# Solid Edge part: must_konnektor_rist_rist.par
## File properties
Author: Romil
Template: iso part.par
Last saved by: Romil
Revision: 24
Application: Solid Edge
Accuracy: 0.990
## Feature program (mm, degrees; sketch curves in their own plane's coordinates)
sketch for "unnamed Protrusion 1" plane through (0, 0, 0) normal (1, 0, 0) x-axis (0, 1, 0)
  circle centre (0, 0) radius 3.35
extrude "unnamed Protrusion 1" add finite 16 symmetric
sketch for "ExtrudedCutout_1" plane through (0, 0, 0) normal (1, 0, 0) x-axis (0, 1, 0)
  circle centre (0, 0) radius 2.55
extrude "ExtrudedCutout_1" cut finite 26.4602 symmetric
sketch for "ExtrudedProtrusion_2" plane through (0, 0, 0) normal (1, 0, 0) x-axis (0, 1, 0)
  circle centre (0, 0) radius 2.85
extrude "ExtrudedProtrusion_2" add finite 1.56 symmetric
sketch for "ExtrudedCutout_2" plane through (0, 0, 0) normal (1, 0, 0) x-axis (0, 1, 0)
  circle centre (0, 0) radius 1.5
extrude "ExtrudedCutout_2" cut finite 517.645 symmetric
sketch for "unnamed Protrusion 2" plane through (-8, 0, 0) normal (-1, 0, 0) x-axis (0, -1, 0)
  line (-1.1715, -2.55) -> (1.1715, -2.55)
  line (1.2205, -2.55) -> (1.1715, -2.55)
  line (1.2763, -2.55) -> (1.2205, -2.55)
  line (0.6382, -1.9118) -> (1.2763, -2.55)
  line (-0.6382, -1.9118) -> (-1.2763, -2.55)
  line (-1.2763, -2.55) -> (-1.2205, -2.55)
  line (-1.2205, -2.55) -> (-1.1715, -2.55)
extrude "unnamed Protrusion 2" add to key point along -normal
mirror "unnamed Mirror 1" of "unnamed Protrusion 2" about plane through (0, 0, 0) normal (0, 0, 1)
extrude "unnamed Protrusion 3" add finite 16
sketch for "unnamed Protrusion 4" plane through (-8, 0, 0) normal (-1, 0, 0) x-axis (0, -1, 0)
  arc centre (-1.65, 0) radius 0.15 from (-1.5, 0) to (-1.65, 0.15) ccw
  line (-1.65, 0.15) -> (-3.1, 0.15)
  line (-3.1, 0.15) -> (-3.1, -0.15)
  line (-3.1, -0.15) -> (-1.65, -0.15)
  arc centre (-1.65, 0) radius 0.15 from (-1.65, -0.15) to (-1.5, 0) ccw
extrude "unnamed Protrusion 4" add to key point along -normal
mirror "unnamed Mirror 2" of "unnamed Protrusion 4" about plane through (0, 0, 0) normal (0, -1, 0)
extrude "unnamed Protrusion 5" add finite 16
sketch for "ExtrudedCutout_3" plane through (-8, 0, 0) normal (-1, 0, 0) x-axis (0, -1, 0)
  circle centre (3.9391, 3.9391) radius 2.45
extrude "ExtrudedCutout_3" cut finite 274.7271 symmetric
mirror "unnamed Mirror 3" of "ExtrudedCutout_3" about plane through (0, 0, 0) normal (0, -1, 0)
extrude "unnamed Cutout 1" cut finite 274.7271 symmetric
mirror "unnamed Mirror 4" of "ExtrudedCutout_3", "unnamed Mirror 3" about plane through (0, 0, 0) normal (0, 0, 1)
extrude "unnamed Cutout 2" cut finite 274.7271 symmetric
extrude "unnamed Cutout 3" cut finite 274.7271 symmetric
sketch for "ExtrudedCutout_7" plane through (-8, 0, 0) normal (-1, 0, 0) x-axis (0, -1, 0)
  line (-3.15, -3.7941) -> (-3.15, 4.9513)
  line (-3.15, 4.9513) -> (-5.3224, 4.9513)
  line (-5.3224, 4.9513) -> (-5.3224, -3.7941)
  line (-5.3224, -3.7941) -> (-3.15, -3.7941)
extrude "ExtrudedCutout_7" cut finite 49.4886 symmetric
mirror "unnamed Mirror 5" of "ExtrudedCutout_7" about plane through (0, 0, 0) normal (0, -1, 0)
extrude "unnamed Cutout 4" cut finite 49.4886 symmetric
fillet "Round_2" radius 0.5
sketch for "unnamed RevolvedProtrusion 1" plane through (0, 0, 0) normal (0, -1, 0) x-axis (1, 0, 0)
  line (0.086, 3.4049) -> (0.4761, 2.7468)
  line (0.4761, 2.7468) -> (0, 2.7468)
  line (-0.4761, 2.7468) -> (0, 2.7468)
  line (-0.086, 3.4049) -> (-0.4761, 2.7468)
  arc centre (0, 3.3539) radius 0.1 from (-0.086, 3.4049) to (0.086, 3.4049) cw
revolve "unnamed RevolvedProtrusion 1" add finite 360 deg
pattern "unnamed Pattern 1" of "unnamed RevolvedProtrusion 1"
revolve "unnamed RevolvedProtrusion 2" add finite 360 deg
revolve "unnamed RevolvedProtrusion 3" add finite 360 deg
sketch for "ExtrudedCutout_16" plane through (8, 0, 0) normal (1, 0, 0) x-axis (0, 0, -1)
  line (-3.512, -1.8908) -> (-1.8908, -3.512)
  arc centre (-3.2512, -3.1128) radius 1.4178 from (-2.0078, -2.4316) to (-1.8908, -3.512) cw
  arc centre (-3.9391, -3.9391) radius 2.45 from (-2.4316, -2.0078) to (-2.0078, -2.4316) cw
  arc centre (-3.1128, -3.2512) radius 1.4178 from (-2.4316, -2.0078) to (-3.512, -1.8908) ccw
extrude "ExtrudedCutout_16" cut finite 89.8858 symmetric
mirror "unnamed Mirror 6" of "ExtrudedCutout_16" about plane through (0, 0, 0) normal (0, 0, 1)
extrude "unnamed Cutout 5" cut finite 89.8858 symmetric
mirror "unnamed Mirror 7" of "ExtrudedCutout_16", "unnamed Mirror 6" about plane through (0, 0, 0) normal (0, -1, 0)
extrude "unnamed Cutout 6" cut finite 89.8858 symmetric
extrude "unnamed Cutout 7" cut finite 89.8858 symmetric
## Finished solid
Body 1: solid body, 183 faces, 536 edges, 356 vertices.
  Faces by surface: cylinder 117, plane 30, cone 24, torus 12
  Edges by curve: intersection 204, line 188, circle 144
Bounding box of the edges (mm; curved faces can reach further): 16.000 x 6.739 x 6.739, from (-8, -3.3697, -3.3697) to (8, 3.3697, 3.3697).
Cylindrical faces by radius (mm): R0.15 x4, R0.5 x48, R0.9025 x4, R1.4178 x24, R1.5 x1, R2.45 x4, R2.55 x8, R3.35 x24
Conical faces (half-angle, radius in mm at the cone's reference point): 59.3426 deg R2.7468 x12, 59.3426 deg R3.4049 x12
Toroidal faces (ring radius, tube radius in mm): R3.3539 r0.1 x12
Planar faces by outward normal: +x 3, +y 2, +z 2, -x 3, -y 2, -z 2, oblique 16
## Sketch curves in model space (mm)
arc centre (8, -3.1128, 3.2512) radius 1.4178 from (8, -2.4316, 2.0078) through (8, -2.9601, 1.8417) to (8, -3.512, 1.8908)
line (8, -1.8908, 3.512) -> (8, -3.512, 1.8908)
arc centre (8, -3.2512, 3.1128) radius 1.4178 from (8, -2.0078, 2.4316) through (8, -1.8417, 2.9601) to (8, -1.8908, 3.512)
arc centre (8, -3.9391, 3.9391) radius 2.45 from (8, -2.0078, 2.4316) through (8, -2.2067, 2.2067) to (8, -2.4316, 2.0078)
line (-1.2676, 0, 0) -> (3.2004, 0, 0)
line (0, 0, 3.55) -> (2.1726, 0, 3.55)
line (-0.4761, 0, 2.7468) -> (0, 0, 2.7468)
line (0.4761, 0, 2.7468) -> (0, 0, 2.7468)
line (0.086, 0, 3.4049) -> (0.4761, 0, 2.7468)
arc centre (0, 0, 3.3539) radius 0.1 from (-0.086, 0, 3.4049) through (0.003, 0, 3.4538) to (0.086, 0, 3.4049)
line (-0.086, 0, 3.4049) -> (-0.4761, 0, 2.7468)
circle centre (-8, -3.9391, 3.9391) radius 2.45
line (-8, 0, 0) -> (-8, -14.3473, 14.3473)
line (-8, 5.3224, 4.9513) -> (-8, 5.3224, -3.7941)
line (-8, 5.3224, -3.7941) -> (-8, 3.15, -3.7941)
line (-8, 3.15, -3.7941) -> (-8, 3.15, 4.9513)
line (-8, 3.15, 4.9513) -> (-8, 5.3224, 4.9513)
line (-8, 1.5, -0.15) -> (-8, 1.5, 0)
arc centre (-8, 1.65, 0) radius 0.15 from (-8, 1.65, -0.15) through (-8, 1.5409, -0.1029) to (-8, 1.5, 0)
arc centre (-8, 1.65, 0) radius 0.15 from (-8, 1.5, 0) through (-8, 1.5471, 0.1091) to (-8, 1.65, 0.15)
line (-8, 1.65, 0.15) -> (-8, 3.1, 0.15)
line (-8, 3.1, 0.15) -> (-8, 3.1, -0.15)
line (-8, 3.1, -0.15) -> (-8, 1.65, -0.15)
arc centre (-8, 1.6038, -1.1788) radius 1.3753 from (-8, 0.6313, -2.1513) through (-8, 0.6363, -2.1563) to (-8, 0.6414, -2.1613)
arc centre (-8, 0, -2.55) radius 0.75 from (-8, 0.6416, -2.1616) through (-8, 0.6415, -2.1615) to (-8, 0.6414, -2.1613)
line (-8, -1.2205, -2.55) -> (-8, -1.1715, -2.55)
line (-8, -1.2763, -2.55) -> (-8, -1.2205, -2.55)
line (-8, -0.6382, -1.9118) -> (-8, -1.2763, -2.55)
arc centre (-8, 0, -2.55) radius 0.9025 from (-8, 0.6382, -1.9118) through (-8, -0.0262, -1.6479) to (-8, -0.6382, -1.9118)
line (-8, 0.6382, -1.9118) -> (-8, 1.2763, -2.55)
line (-8, 1.2763, -2.55) -> (-8, 1.2205, -2.55)
line (-8, 1.2205, -2.55) -> (-8, 1.1715, -2.55)
line (-8, 1.1715, -2.55) -> (-8, -1.1715, -2.55)
circle centre (0, 0, 0) radius 1.5
circle centre (0, 0, 0) radius 2.85
circle centre (0, 0, 0) radius 3.35
circle centre (0, 0, 0) radius 2.55
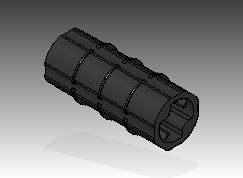
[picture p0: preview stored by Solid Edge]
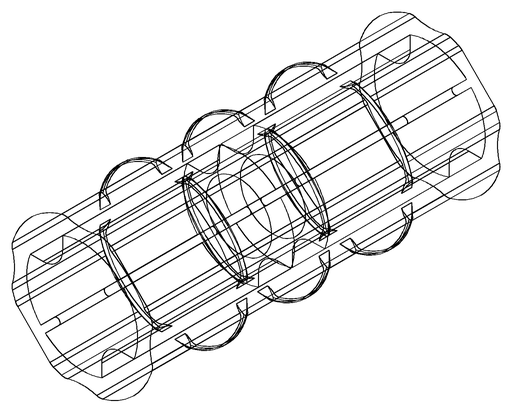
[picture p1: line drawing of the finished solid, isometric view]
